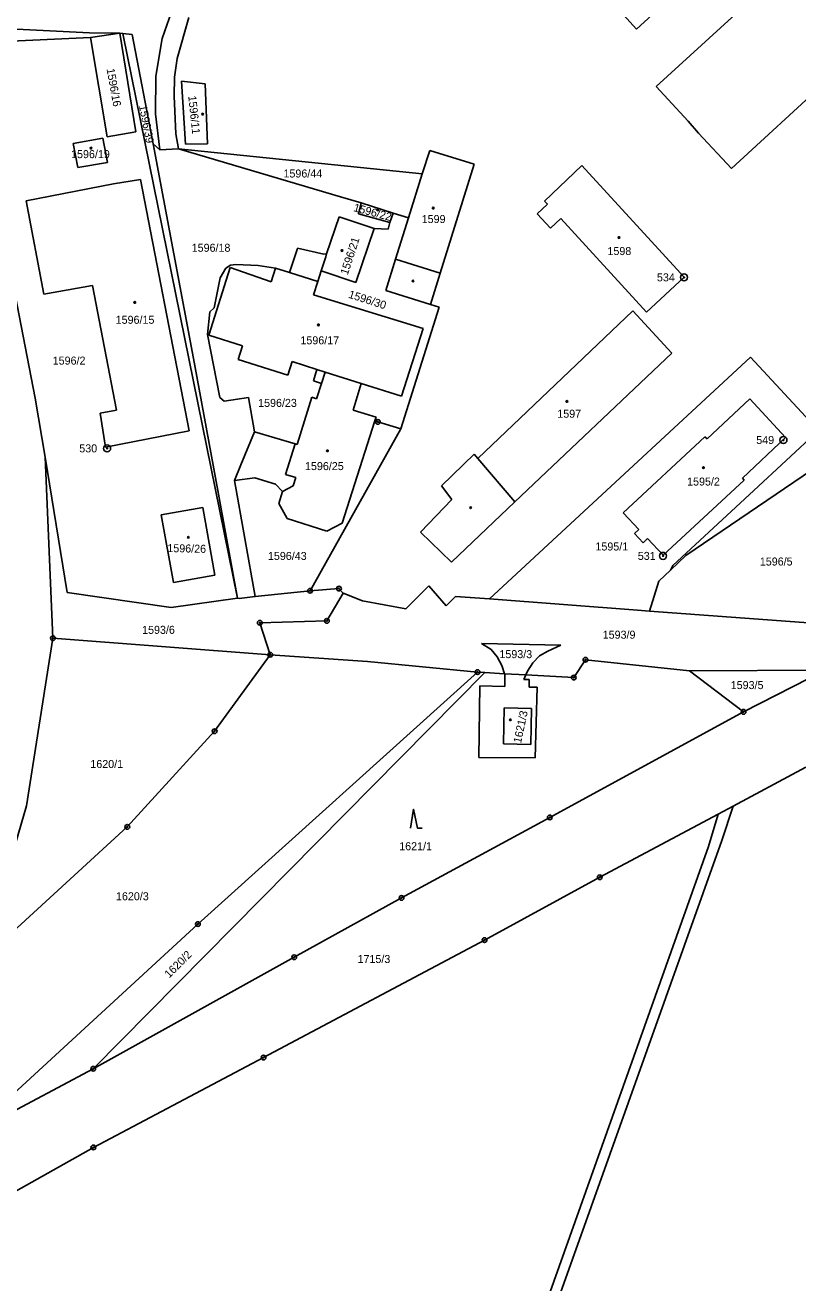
# Model space of a CAD drawing. Extents: x -763296 to -761805, y -1153670 to -1152034.
# Drawn here: x -762483 to -762319, y -1153075 to -1152808 of the extents above; entities that cross this region are included whole.
import ezdxf

# ---------------------------------------------------------------- set-up
doc = ezdxf.new("R2010")
doc.units = 0
for name, color, linetype in [('Vrstva 1', 7, 'Continuous'), ('Vrstva 17', 7, 'Continuous'), ('Vrstva 18', 7, 'Continuous'), ('Vrstva 19', 7, 'Continuous'), ('Vrstva 24', 7, 'Continuous'), ('Vrstva 25', 7, 'Continuous'), ('Vrstva 4', 7, 'Continuous'), ('Vrstva 6', 7, 'Continuous')]:
    doc.layers.add(name, color=color, linetype=linetype)

msp = doc.modelspace()

# ---------------------------------------------------------------- linework, layer by layer
at = {"layer": 'Vrstva 1'}
for p, q in [((-762337.37, -1152794.13), (-762353.25, -1152808.84)), ((-762353.25, -1152808.84), (-762361.9, -1152799.22)), ((-762349.07, -1152820.98), (-762327.17, -1152800.94)), ((-762453.95, -1152810.83), (-762451.93, -1152805.15)), ((-762448.3, -1152806.34), (-762450.74, -1152815.01)), ((-762469.39, -1152809.59), (-762492.69, -1152808.38)), ((-762469.13, -1152810.58), (-762492.22, -1152811.65)), ((-762462.93, -1152809.65), (-762469.39, -1152809.59)), ((-762462.93, -1152809.65), (-762469.13, -1152810.58)), ((-762469.13, -1152810.58), (-762465.63, -1152831.66)), ((-762462.27, -1152809.73), (-762462.93, -1152809.65)), ((-762462.93, -1152809.65), (-762459.52, -1152830.62)), ((-762437.93, -1152929.63), (-762462.27, -1152809.73)), ((-762460.27, -1152809.97), (-762462.27, -1152809.73)), ((-762455.84, -1152833.17), (-762460.27, -1152809.97)), ((-762495.62, -1152811.48), (-762480.87, -1152887.2)), ((-762455.3, -1152818.77), (-762453.95, -1152810.83)), ((-762450.74, -1152815.01), (-762451.29, -1152818.99)), ((-762333.07, -1152838.41), (-762308.09, -1152815.37)), ((-762455.35, -1152826.79), (-762455.3, -1152818.77)), ((-762451.29, -1152818.99), (-762451.4, -1152823.03)), ((-762449, -1152833.23), (-762449.83, -1152819.85)), ((-762449.83, -1152819.85), (-762444.82, -1152820.43)), ((-762444.82, -1152820.43), (-762444.33, -1152833.14)), ((-762342.31, -1152828.33), (-762349.07, -1152820.98)), ((-762451.4, -1152823.03), (-762451.02, -1152831.04)), ((-762454.43, -1152834.46), (-762455.35, -1152826.79)), ((-762340.06, -1152830.9), (-762342.31, -1152828.33)), ((-762472.79, -1152833.12), (-762466.5, -1152831.93)), ((-762466.5, -1152831.93), (-762465.53, -1152837.11)), ((-762465.63, -1152831.66), (-762459.52, -1152830.62)), ((-762451.02, -1152831.04), (-762450.47, -1152834.22)), ((-762333.07, -1152838.41), (-762340.06, -1152830.9)), ((-762471.84, -1152838.18), (-762472.79, -1152833.12)), ((-762447.09, -1152879.89), (-762455.84, -1152833.17)), ((-762455.84, -1152833.17), (-762454.43, -1152834.46)), ((-762454.43, -1152834.46), (-762450.47, -1152834.22)), ((-762450.47, -1152834.22), (-762398.71, -1152839.55)), ((-762450.47, -1152834.22), (-762419.16, -1152843.48)), ((-762444.33, -1152833.14), (-762449, -1152833.23)), ((-762397.15, -1152834.56), (-762398.71, -1152839.55)), ((-762387.69, -1152837.5), (-762397.15, -1152834.56)), ((-762465.53, -1152837.11), (-762471.84, -1152838.18)), ((-762394.89, -1152860.6), (-762387.69, -1152837.5)), ((-762398.71, -1152839.55), (-762401.61, -1152848.86)), ((-762372.75, -1152845.31), (-762364.88, -1152837.77)), ((-762364.88, -1152837.77), (-762343.11, -1152861.47)), ((-762482.78, -1152845.26), (-762464.23, -1152841.68)), ((-762464.23, -1152841.68), (-762458.55, -1152840.73)), ((-762458.55, -1152840.73), (-762448.22, -1152894.08)), ((-762479.04, -1152865.11), (-762482.78, -1152845.26)), ((-762419.16, -1152843.48), (-762416.09, -1152844.39)), ((-762416.09, -1152844.39), (-762411.68, -1152845.69)), ((-762372.12, -1152846), (-762372.75, -1152845.31)), ((-762412.26, -1152848), (-762411.68, -1152845.69)), ((-762405.59, -1152849.89), (-762412.26, -1152848)), ((-762411.68, -1152845.69), (-762404.9, -1152847.85)), ((-762404.9, -1152847.85), (-762405.59, -1152849.89)), ((-762404.9, -1152847.85), (-762401.61, -1152848.86)), ((-762374.3, -1152848), (-762372.12, -1152846)), ((-762371.51, -1152851.04), (-762374.3, -1152848)), ((-762416.36, -1152848.63), (-762419.08, -1152856.55)), ((-762408.94, -1152851.12), (-762416.36, -1152848.63)), ((-762405.59, -1152849.89), (-762405.97, -1152851.31)), ((-762401.61, -1152848.86), (-762404.38, -1152857.65)), ((-762369.33, -1152849.04), (-762371.51, -1152851.04)), ((-762351.11, -1152868.88), (-762369.33, -1152849.04)), ((-762408.94, -1152851.12), (-762412.84, -1152862.62)), ((-762405.97, -1152851.31), (-762408.94, -1152851.12)), ((-762426.91, -1152860.5), (-762425.28, -1152855.58)), ((-762425.28, -1152855.58), (-762425.19, -1152855.3)), ((-762425.19, -1152855.3), (-762419.65, -1152856.56)), ((-762438.26, -1152858.79), (-762439.42, -1152858.91)), ((-762433.56, -1152859.01), (-762438.26, -1152858.79)), ((-762419.2, -1152857.15), (-762420.2, -1152860.1)), ((-762419.65, -1152856.56), (-762419.08, -1152856.55)), ((-762419.08, -1152856.55), (-762419.2, -1152857.15)), ((-762404.38, -1152857.65), (-762406.47, -1152864.31)), ((-762444.05, -1152873.78), (-762439.49, -1152859.42)), ((-762440.42, -1152859.54), (-762441.59, -1152861.61)), ((-762439.42, -1152858.91), (-762440.42, -1152859.54)), ((-762439.49, -1152859.42), (-762430.77, -1152862.43)), ((-762429.87, -1152859.58), (-762433.56, -1152859.01)), ((-762430.77, -1152862.43), (-762429.87, -1152859.58)), ((-762429.87, -1152859.58), (-762426.91, -1152860.5)), ((-762420.2, -1152860.1), (-762420.91, -1152862.37)), ((-762412.84, -1152862.62), (-762420.2, -1152860.1)), ((-762396.98, -1152867.31), (-762394.89, -1152860.6)), ((-762343.11, -1152861.47), (-762351.11, -1152868.88)), ((-762468.72, -1152863.23), (-762479.04, -1152865.11)), ((-762463.62, -1152889.73), (-762468.72, -1152863.23)), ((-762441.59, -1152861.61), (-762442.9, -1152867.99)), ((-762420.91, -1152862.37), (-762421.8, -1152865.25)), ((-762421.8, -1152865.25), (-762398.56, -1152872.39)), ((-762406.47, -1152864.31), (-762396.98, -1152867.31)), ((-762443.78, -1152868.82), (-762444.29, -1152873.63)), ((-762442.9, -1152867.99), (-762443.78, -1152868.82)), ((-762395.1, -1152867.87), (-762403.26, -1152893.68)), ((-762396.98, -1152867.31), (-762395.1, -1152867.87)), ((-762386.93, -1152899.98), (-762354.01, -1152868.62)), ((-762354.01, -1152868.62), (-762345.73, -1152877.59)), ((-762444.29, -1152873.63), (-762441.68, -1152887.02)), ((-762436.86, -1152876.06), (-762444.05, -1152873.78)), ((-762398.56, -1152872.39), (-762403.1, -1152886.76)), ((-762437.78, -1152878.96), (-762436.86, -1152876.06)), ((-762442, -1152907.52), (-762447.09, -1152879.89)), ((-762427.26, -1152882.29), (-762437.78, -1152878.96)), ((-762426.35, -1152879.41), (-762427.26, -1152882.29)), ((-762421.08, -1152881.08), (-762426.35, -1152879.41)), ((-762329.04, -1152878.48), (-762384.48, -1152929.81)), ((-762345.73, -1152877.59), (-762379.05, -1152909.21)), ((-762329.04, -1152878.48), (-762314.62, -1152894.05)), ((-762421.84, -1152883.49), (-762421.08, -1152881.08)), ((-762419.31, -1152881.63), (-762421.08, -1152881.08)), ((-762411.72, -1152884.03), (-762419.31, -1152881.63)), ((-762420.09, -1152884.04), (-762421.84, -1152883.49)), ((-762421.14, -1152887.3), (-762420.09, -1152884.04)), ((-762413.41, -1152889.73), (-762411.72, -1152884.03)), ((-762403.1, -1152886.76), (-762411.72, -1152884.03)), ((-762478.8, -1152899.7), (-762480.87, -1152887.2)), ((-762441.68, -1152887.02), (-762440.8, -1152887.81)), ((-762440.8, -1152887.81), (-762435.58, -1152887.05)), ((-762435.58, -1152887.05), (-762434.35, -1152894.32)), ((-762425.26, -1152896.97), (-762422.14, -1152886.97)), ((-762422.14, -1152886.97), (-762421.14, -1152887.3)), ((-762329.16, -1152887.34), (-762338.28, -1152895.8)), ((-762329.16, -1152887.34), (-762321.61, -1152895.54)), ((-762467.06, -1152890.33), (-762463.62, -1152889.73)), ((-762465.97, -1152897.57), (-762467.06, -1152890.33)), ((-762408.53, -1152891.2), (-762413.41, -1152889.73)), ((-762415.72, -1152913.73), (-762408.78, -1152892)), ((-762408.78, -1152892), (-762408.53, -1152891.2)), ((-762408.78, -1152892), (-762408.14, -1152892.2)), ((-762408.14, -1152892.2), (-762403.26, -1152893.68)), ((-762448.22, -1152894.08), (-762465.97, -1152897.57)), ((-762437.24, -1152901.34), (-762434.35, -1152894.32)), ((-762434.35, -1152894.32), (-762425.73, -1152896.86)), ((-762422.54, -1152928.05), (-762403.26, -1152893.68)), ((-762338.74, -1152895.4), (-762356.09, -1152911.48)), ((-762338.28, -1152895.8), (-762338.74, -1152895.4)), ((-762330.78, -1152904.12), (-762321.61, -1152895.54)), ((-762314.62, -1152894.05), (-762328.32, -1152906.75)), ((-762425.73, -1152896.86), (-762425.26, -1152896.97)), ((-762478.8, -1152899.7), (-762477.12, -1152938.13)), ((-762474.12, -1152928.41), (-762478.8, -1152899.7)), ((-762437.24, -1152901.34), (-762438.61, -1152904.67)), ((-762394.62, -1152905.75), (-762387.67, -1152899.06)), ((-762387.67, -1152899.06), (-762386.93, -1152899.98)), ((-762342.77, -1152920.57), (-762314.13, -1152901.12)), ((-762434.26, -1152904.08), (-762438.61, -1152904.67)), ((-762429.91, -1152905.41), (-762434.26, -1152904.08)), ((-762330.37, -1152904.56), (-762330.78, -1152904.12)), ((-762438.61, -1152904.67), (-762434.18, -1152929.26)), ((-762428.36, -1152906.98), (-762429.91, -1152905.41)), ((-762392.48, -1152908.67), (-762394.62, -1152905.75)), ((-762347.59, -1152920.53), (-762330.37, -1152904.56)), ((-762345.53, -1152922.71), (-762328.32, -1152906.75)), ((-762437.93, -1152929.63), (-762442, -1152907.52)), ((-762428.36, -1152906.98), (-762429.17, -1152909.52)), ((-762429.17, -1152909.52), (-762427.43, -1152912.74)), ((-762399.13, -1152915.6), (-762392.48, -1152908.67)), ((-762379.05, -1152909.21), (-762392.53, -1152922.01)), ((-762454.17, -1152911.95), (-762445.33, -1152910.35)), ((-762451.56, -1152926.34), (-762454.17, -1152911.95)), ((-762445.33, -1152910.35), (-762442.73, -1152924.75)), ((-762356.09, -1152911.48), (-762352.77, -1152915.02)), ((-762427.43, -1152912.74), (-762418.99, -1152915.38)), ((-762418.99, -1152915.38), (-762415.72, -1152913.73)), ((-762392.53, -1152922.01), (-762399.13, -1152915.6)), ((-762352.77, -1152915.02), (-762353.7, -1152915.89)), ((-762353.7, -1152915.89), (-762351.86, -1152917.85)), ((-762351.86, -1152917.85), (-762350.93, -1152916.98)), ((-762350.93, -1152916.98), (-762347.59, -1152920.53)), ((-762346.02, -1152923.66), (-762342.77, -1152920.57)), ((-762346.02, -1152923.66), (-762345.53, -1152922.71)), ((-762442.73, -1152924.75), (-762451.56, -1152926.34)), ((-762348.51, -1152926.03), (-762346.02, -1152923.66)), ((-762434.18, -1152929.26), (-762422.54, -1152928.05)), ((-762422.54, -1152928.05), (-762416.4, -1152927.61)), ((-762416.4, -1152927.61), (-762415.51, -1152928.57)), ((-762402.19, -1152931.91), (-762397.34, -1152927.04)), ((-762393.63, -1152931.29), (-762397.34, -1152927.04)), ((-762350.49, -1152932.38), (-762348.51, -1152926.03)), ((-762452.03, -1152931.61), (-762474.12, -1152928.41)), ((-762437.93, -1152929.63), (-762452.03, -1152931.61)), ((-762437.56, -1152929.7), (-762437.93, -1152929.63)), ((-762434.18, -1152929.26), (-762437.56, -1152929.7)), ((-762415.51, -1152928.57), (-762418.97, -1152934.45)), ((-762415.51, -1152928.57), (-762411.44, -1152930.18)), ((-762411.44, -1152930.18), (-762402.19, -1152931.91)), ((-762391.64, -1152929.26), (-762393.63, -1152931.29)), ((-762384.48, -1152929.81), (-762391.64, -1152929.26)), ((-762353.03, -1152932.21), (-762384.48, -1152929.81)), ((-762350.49, -1152932.38), (-762353.03, -1152932.21)), ((-762308.45, -1152935.46), (-762350.49, -1152932.38)), ((-762418.97, -1152934.45), (-762433.2, -1152934.87)), ((-762433.2, -1152934.87), (-762430.99, -1152941.66)), ((-762477.12, -1152938.13), (-762482.73, -1152973.76)), ((-762477.12, -1152938.13), (-762430.99, -1152941.66)), ((-762430.99, -1152941.66), (-762442.79, -1152957.89)), ((-762430.99, -1152941.66), (-762410.38, -1152943.05)), ((-762384.11, -1152940.55), (-762386.15, -1152939.27)), ((-762386.15, -1152939.27), (-762369.3, -1152939.61)), ((-762382.8, -1152942.12), (-762384.11, -1152940.55)), ((-762372.09, -1152940.88), (-762373.86, -1152941.87)), ((-762369.3, -1152939.61), (-762372.09, -1152940.88)), ((-762410.38, -1152943.05), (-762386.98, -1152945.34)), ((-762381.82, -1152943.9), (-762382.8, -1152942.12)), ((-762381.27, -1152945.67), (-762381.82, -1152943.9)), ((-762375.28, -1152943.34), (-762376.39, -1152945.17)), ((-762373.86, -1152941.87), (-762375.28, -1152943.34)), ((-762366.56, -1152946.51), (-762364.1, -1152942.72)), ((-762364.1, -1152942.72), (-762342.03, -1152945.09)), ((-762385.45, -1152945.43), (-762468.55, -1153029.57)), ((-762386.98, -1152945.34), (-762446.36, -1152998.85)), ((-762386.98, -1152945.34), (-762385.45, -1152945.43)), ((-762385.45, -1152945.43), (-762381.27, -1152945.67)), ((-762381.23, -1152945.81), (-762381.27, -1152945.67)), ((-762381.27, -1152945.67), (-762376.74, -1152945.93)), ((-762381.23, -1152948.38), (-762381.23, -1152945.81)), ((-762376.74, -1152945.93), (-762377.19, -1152946.89)), ((-762377.19, -1152946.89), (-762376.01, -1152946.91)), ((-762376.39, -1152945.17), (-762376.74, -1152945.93)), ((-762376.74, -1152945.93), (-762366.56, -1152946.51)), ((-762376.01, -1152946.91), (-762376.01, -1152948.5)), ((-762342.03, -1152945.09), (-762330.53, -1152953.77)), ((-762330.53, -1152953.77), (-762313.17, -1152944.94)), ((-762386.72, -1152963.48), (-762386.52, -1152948.25)), ((-762386.52, -1152948.25), (-762381.23, -1152948.38)), ((-762376.01, -1152948.5), (-762374.36, -1152948.54)), ((-762374.36, -1152948.54), (-762374.76, -1152963.55)), ((-762371.65, -1152976.18), (-762330.53, -1152953.77)), ((-762442.79, -1152957.89), (-762461.33, -1152978.19)), ((-762374.76, -1152963.55), (-762386.72, -1152963.48)), ((-762332.73, -1152973.78), (-762317.29, -1152965.54)), ((-762482.73, -1152973.76), (-762489.42, -1152996.62)), ((-762371.65, -1152976.18), (-762403.12, -1152993.28)), ((-762361.05, -1152988.89), (-762335.9, -1152975.47)), ((-762337.96, -1152982.34), (-762335.9, -1152975.47)), ((-762335.9, -1152975.47), (-762332.73, -1152973.78)), ((-762335.11, -1152981.09), (-762332.73, -1152973.78)), ((-762461.33, -1152978.19), (-762497.75, -1153011.54)), ((-762394.86, -1153148.62), (-762335.11, -1152981.09)), ((-762337.96, -1152982.34), (-762397.62, -1153150.18)), ((-762385.5, -1153002.25), (-762361.05, -1152988.89)), ((-762403.12, -1152993.28), (-762425.9, -1153005.88)), ((-762446.36, -1152998.85), (-762495.08, -1153043.69)), ((-762432.42, -1153027.18), (-762385.5, -1153002.25)), ((-762425.9, -1153005.88), (-762468.55, -1153029.57)), ((-762468.55, -1153029.57), (-762495.08, -1153043.69)), ((-762432.42, -1153027.18), (-762468.54, -1153046.27)), ((-762468.54, -1153046.27), (-762499.07, -1153063.48))]:
    msp.add_line(p, q, dxfattribs=at)
at = {"layer": 'Vrstva 24'}
for centre, radius in [((-762343.15, -1152861.51), 0.75), ((-762343.15, -1152861.51), 0.1), ((-762408.14, -1152892.2), 0.5), ((-762408.14, -1152892.2), 0.1), ((-762322.06, -1152896.05), 0.75), ((-762322.06, -1152896.05), 0.1), ((-762465.62, -1152897.83), 0.75), ((-762465.62, -1152897.83), 0.1), ((-762347.62, -1152920.66), 0.75), ((-762347.62, -1152920.66), 0.1), ((-762422.54, -1152928.05), 0.5), ((-762422.54, -1152928.05), 0.1), ((-762416.4, -1152927.61), 0.5), ((-762416.4, -1152927.61), 0.1), ((-762433.2, -1152934.87), 0.5), ((-762433.2, -1152934.87), 0.1), ((-762418.97, -1152934.45), 0.5), ((-762418.97, -1152934.45), 0.1), ((-762477.12, -1152938.13), 0.5), ((-762477.12, -1152938.13), 0.1), ((-762430.99, -1152941.66), 0.5), ((-762430.99, -1152941.66), 0.1), ((-762364.1, -1152942.72), 0.5), ((-762364.1, -1152942.72), 0.1), ((-762386.98, -1152945.34), 0.5), ((-762386.98, -1152945.34), 0.1), ((-762366.56, -1152946.51), 0.5), ((-762366.56, -1152946.51), 0.1), ((-762330.53, -1152953.77), 0.5), ((-762330.53, -1152953.77), 0.1), ((-762442.79, -1152957.89), 0.5), ((-762442.79, -1152957.89), 0.1), ((-762371.65, -1152976.18), 0.5), ((-762371.65, -1152976.18), 0.1), ((-762461.33, -1152978.19), 0.5), ((-762461.33, -1152978.19), 0.1), ((-762361.05, -1152988.89), 0.5), ((-762361.05, -1152988.89), 0.1), ((-762403.12, -1152993.28), 0.5), ((-762403.12, -1152993.28), 0.1), ((-762446.36, -1152998.85), 0.5), ((-762446.36, -1152998.85), 0.1), ((-762385.5, -1153002.25), 0.5), ((-762385.5, -1153002.25), 0.1), ((-762425.9, -1153005.88), 0.5), ((-762425.9, -1153005.88), 0.1), ((-762432.42, -1153027.18), 0.5), ((-762432.42, -1153027.18), 0.1), ((-762468.55, -1153029.57), 0.5), ((-762468.55, -1153029.57), 0.1), ((-762468.54, -1153046.27), 0.5), ((-762468.54, -1153046.27), 0.1)]:
    msp.add_circle(centre, radius, dxfattribs=at)
at = {"layer": 'Vrstva 25'}
msp.add_lwpolyline([(-762401.25, -1152978.46), (-762400.55, -1152974.46), (-762399.75, -1152978.46), (-762398.75, -1152978.46)], dxfattribs=at)
for centre in [(-762445.32, -1152826.85), (-762469.04, -1152834.08), (-762408.11, -1152847.21), (-762396.39, -1152846.82), (-762356.95, -1152853.06), (-762415.75, -1152855.82), (-762400.7, -1152862.28), (-762459.74, -1152866.85), (-762420.76, -1152871.61), (-762368.03, -1152887.86), (-762418.85, -1152898.35), (-762339.04, -1152901.92), (-762388.46, -1152910.42), (-762448.36, -1152916.7), (-762380.01, -1152955.47)]:
    msp.add_circle(centre, 0.175, dxfattribs=at)
at = {"layer": 'Vrstva 4'}
for p, q in [((-762404.38, -1152857.65), (-762394.89, -1152860.6)), ((-762426.91, -1152860.5), (-762420.91, -1152862.37)), ((-762420.09, -1152884.04), (-762419.31, -1152881.63)), ((-762425.73, -1152896.86), (-762427.76, -1152903.35)), ((-762386.93, -1152899.98), (-762379.05, -1152909.21)), ((-762427.76, -1152903.35), (-762425.58, -1152904.03)), ((-762425.58, -1152904.03), (-762426.13, -1152905.79)), ((-762426.13, -1152905.79), (-762428.36, -1152906.98)), ((-762381.51, -1152960.57), (-762381.36, -1152952.94)), ((-762381.36, -1152952.94), (-762375.52, -1152953.03)), ((-762375.52, -1152953.03), (-762375.68, -1152960.69)), ((-762375.68, -1152960.69), (-762381.51, -1152960.57))]:
    msp.add_line(p, q, dxfattribs=at)
at = {"layer": 'Vrstva 6'}
msp.add_line((-762342.03, -1152945.09), (-762313.17, -1152944.94), dxfattribs=at)

# ---------------------------------------------------------------- texts
at = {"layer": 'Vrstva 17'}
for s, p in [('534', (-762348.904, -1152862.36)), ('549', (-762327.827, -1152896.9)), ('530', (-762471.521, -1152898.68)), ('531', (-762352.972, -1152921.51))]:
    msp.add_text(s, height=1.7, dxfattribs=at).set_placement(p)
at = {"layer": 'Vrstva 18'}
for s, rotation, p in [('1596/16', 280.29095, (-762465.744, -1152817.284)), ('1596/39', 280.86391, (-762458.867, -1152825.085)), ('1596/30', 342.28499, (-762414.525, -1152865.813)), ('1620/2', 44.97719, (-762452.433, -1153010.411))]:
    msp.add_text(s, height=1.7, rotation=rotation, dxfattribs=at).set_placement(p)
for s, p in [('1596/44', (-762428.181, -1152840.31)), ('1596/18', (-762447.663, -1152856.08)), ('1596/2', (-762477.165, -1152880.04)), ('1596/23', (-762433.561, -1152889.02)), ('1596/43', (-762431.478, -1152921.52)), ('1595/1', (-762361.96, -1152919.51)), ('1596/5', (-762327.068, -1152922.7)), ('1593/6', (-762458.188, -1152937.21)), ('1593/9', (-762360.418, -1152938.24)), ('1593/3', (-762382.345, -1152942.37)), ('1593/5', (-762333.245, -1152948.94)), ('1620/1', (-762469.177, -1152965.7)), ('1621/1', (-762403.612, -1152983.16)), ('1620/3', (-762463.732, -1152993.78)), ('1715/3', (-762412.46, -1153007.1))]:
    msp.add_text(s, height=1.7, dxfattribs=at).set_placement(p)
at = {"layer": 'Vrstva 19'}
for s, rotation, p in [('1596/11', 276.16566, (-762448.41, -1152823.028)), ('1596/22', 344.97789, (-762413.439, -1152847.433)), ('1596/21', 71.9062, (-762414.556, -1152861.127)), ('1596/26', 358.72888, (-762452.843, -1152919.838)), ('1621/3', 77.97956, (-762377.757, -1152960.528))]:
    msp.add_text(s, height=1.7, rotation=rotation, dxfattribs=at).set_placement(p)
for s, p in [('1596/19', (-762473.263, -1152836.2)), ('1599', (-762398.842, -1152849.98)), ('1598', (-762359.412, -1152856.78)), ('1596/15', (-762463.799, -1152871.37)), ('1596/17', (-762424.582, -1152875.73)), ('1597', (-762370.062, -1152891.32)), ('1596/25', (-762423.611, -1152902.44)), ('1595/2', (-762342.502, -1152905.72))]:
    msp.add_text(s, height=1.7, dxfattribs=at).set_placement(p)

doc.saveas('drawing.dxf')
